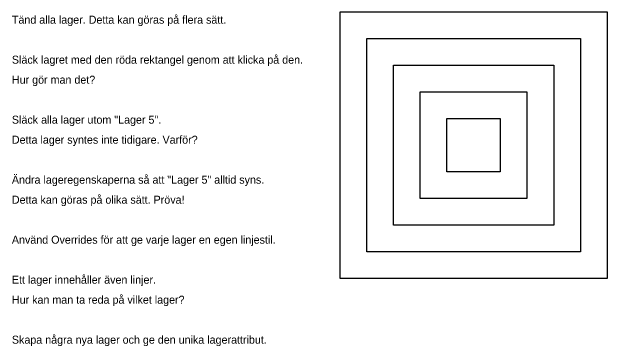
# Model space of a CAD drawing. Extents: x 1517688.1 to 1517710.4, y 6495352 to 6495364.5.
import ezdxf

# ---------------------------------------------------------------- set-up
doc = ezdxf.new("R2010")
doc.units = 0
for name, color, linetype in [('Instruktioner', 7, 'Continuous'), ('Lager 1', 7, 'Continuous'), ('Lager 2', 7, 'Continuous'), ('Lager 3', 7, 'Continuous'), ('Lager 4', 7, 'Continuous'), ('Lager 5', 7, 'Continuous')]:
    doc.layers.add(name, color=color, linetype=linetype)

msp = doc.modelspace()

# ---------------------------------------------------------------- linework, layer by layer
at = {"layer": 'Lager 1'}
msp.add_lwpolyline([(1517700.355, 6495364.497), (1517710.355, 6495364.497), (1517710.355, 6495354.497), (1517700.355, 6495354.497)], close=True, dxfattribs=at)
at = {"layer": 'Lager 2'}
for p, q in [((1517701.355, 6495355.497), (1517701.355, 6495363.497)), ((1517701.355, 6495363.497), (1517709.355, 6495363.497)), ((1517709.355, 6495363.497), (1517709.355, 6495355.497)), ((1517709.355, 6495355.497), (1517701.355, 6495355.497))]:
    msp.add_line(p, q, dxfattribs=at)
msp.add_lwpolyline([(1517701.355, 6495363.497), (1517709.355, 6495363.497), (1517709.355, 6495355.497), (1517701.355, 6495355.497)], close=True, dxfattribs=at)
at = {"layer": 'Lager 3'}
msp.add_lwpolyline([(1517702.355, 6495362.497), (1517708.355, 6495362.497), (1517708.355, 6495356.497), (1517702.355, 6495356.497)], close=True, dxfattribs=at)
at = {"layer": 'Lager 4'}
msp.add_lwpolyline([(1517703.355, 6495361.497), (1517707.355, 6495361.497), (1517707.355, 6495357.497), (1517703.355, 6495357.497)], close=True, dxfattribs=at)
at = {"layer": 'Lager 5'}
msp.add_lwpolyline([(1517704.355, 6495360.497), (1517706.355, 6495360.497), (1517706.355, 6495358.497), (1517704.355, 6495358.497)], close=True, dxfattribs=at)

# ---------------------------------------------------------------- texts
at = {"layer": 'Instruktioner'}
for s, p in [('Tänd alla lager. Detta kan göras på flera sätt. ', (1517688.065, 6495364.054)), ('Släck lagret med den röda rektangel genom att klicka på den.', (1517688.065, 6495362.554)), ('Hur gör man det?', (1517688.065, 6495361.804)), ('Släck alla lager utom "Lager 5". ', (1517688.065, 6495360.304)), ('Detta lager syntes inte tidigare. Varför?', (1517688.065, 6495359.554)), ('Ändra lageregenskaperna så att "Lager 5" alltid syns.', (1517688.065, 6495358.054)), ('Detta kan göras på olika sätt. Pröva!', (1517688.065, 6495357.304)), ('Använd Overrides för att ge varje lager en egen linjestil.', (1517688.065, 6495355.804)), ('Ett lager innehåller även linjer. ', (1517688.065, 6495354.304)), ('Hur kan man ta reda på vilket lager?', (1517688.065, 6495353.554)), ('Skapa några nya lager och ge den unika lagerattribut.', (1517688.065, 6495352.054))]:
    msp.add_text(s, height=0.3, dxfattribs=at).set_placement(p)

doc.saveas('drawing.dxf')
